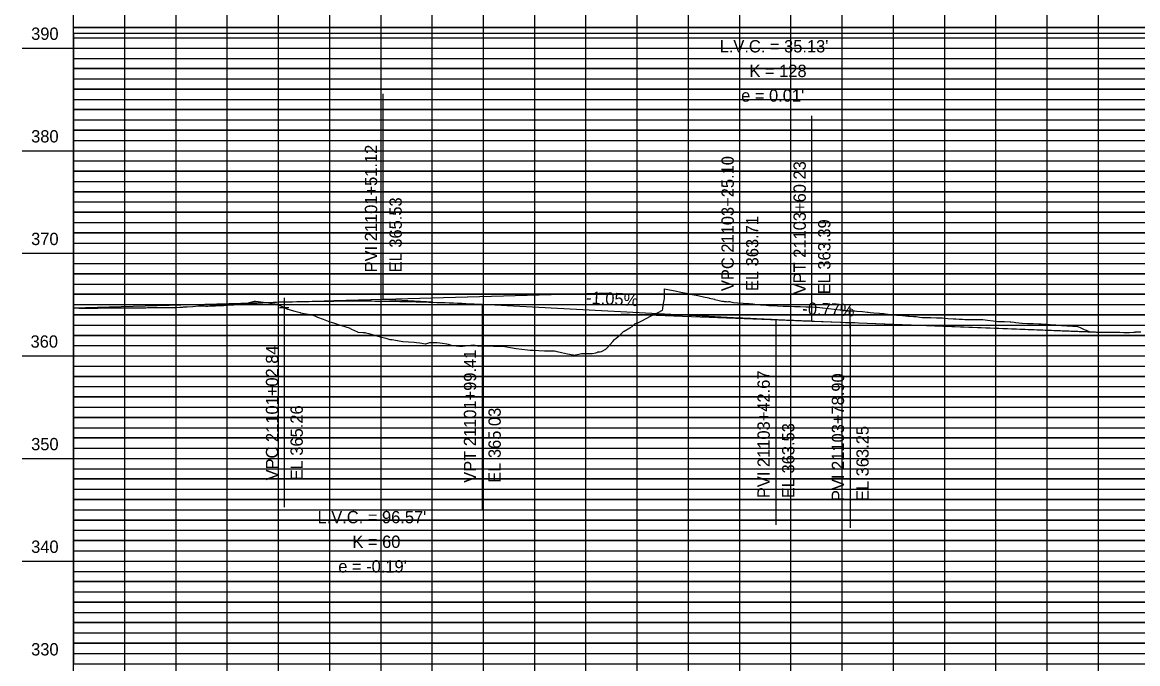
# Model space of a CAD drawing. Extents: x 1195880 to 1289360, y 2059330 to 2086925.
# Drawn here: x 1197037 to 1197582, y 2060795 to 2061108 of the extents above; entities that cross this region are included whole.
import ezdxf

# ---------------------------------------------------------------- set-up
doc = ezdxf.new("R2010")
doc.units = 0
for name, color, linetype in [('Clip', 7, 'Continuous'), ('Default', 7, 'Continuous'), ('Existing Ground PGL', 7, 'Continuous'), ('Grid', 7, 'Continuous'), ('Grid Lables', 7, 'Continuous'), ('Profile', 7, 'Continuous'), ('Profile Annotation', 7, 'Continuous')]:
    doc.layers.add(name, color=color, linetype=linetype)

msp = doc.modelspace()

# ---------------------------------------------------------------- linework, layer by layer
at = {"layer": 'Clip'}
msp.add_lwpolyline([(1197062.41, 2060795.23), (1197749.67, 2060795.23), (1197749.67, 2061102.29), (1197062.41, 2061102.29)], close=True, dxfattribs=at)
at = {"layer": 'Default'}
for p, q in [((1197062.41, 2060968.63), (1197324.45, 2060976.03)), ((1197165.25, 2060966.92), (1197165.25, 2060973.5)), ((1197162.75, 2060971.53), (1197167.48, 2060971.53)), ((1197162.91, 2060968.78), (1197167.48, 2060968.78)), ((1197438.95, 2060967.23), (1197443.57, 2060967.23)), ((1197441.31, 2060958.74), (1197441.31, 2060968.76)), ((1197329.61, 2060965.79), (1197560.99, 2060956.87)), ((1197438.95, 2060961.48), (1197443.57, 2060961.48))]:
    msp.add_line(p, q, dxfattribs=at)
at = {"layer": 'Existing Ground PGL'}
msp.add_lwpolyline([(1197062.41, 2060968.63), (1197064.09, 2060968.63), (1197065.18, 2060968.53), (1197065.19, 2060968.53), (1197065.95, 2060968.5), (1197066.05, 2060968.47), (1197067.95, 2060968.49), (1197069.77, 2060968.51), (1197070.72, 2060968.52), (1197073.49, 2060968.55), (1197074.28, 2060968.55), (1197076.25, 2060968.57), (1197077.47, 2060968.58), (1197079.02, 2060968.59), (1197081.09, 2060968.6), (1197081.79, 2060968.6), (1197083.51, 2060968.62), (1197084.56, 2060968.63), (1197084.89, 2060968.63), (1197087.33, 2060968.65), (1197088.65, 2060968.65), (1197090.1, 2060968.67), (1197091.99, 2060968.68), (1197092.87, 2060968.69), (1197093.23, 2060968.69), (1197095.64, 2060968.7), (1197096.24, 2060968.7), (1197097.36, 2060968.72), (1197097.75, 2060968.72), (1197098.41, 2060968.73), (1197101.17, 2060968.75), (1197101.19, 2060968.75), (1197102.71, 2060968.76), (1197103.94, 2060968.77), (1197104.75, 2060968.77), (1197106.71, 2060968.79), (1197107.16, 2060968.8), (1197108.1, 2060968.8), (1197109.48, 2060968.82), (1197111.2, 2060968.84), (1197111.29, 2060968.84), (1197111.63, 2060968.84), (1197112.25, 2060968.87), (1197114.32, 2060968.96), (1197114.97, 2060968.99), (1197115.02, 2060969), (1197115.75, 2060969.04), (1197116.08, 2060969.06), (1197117.79, 2060969.18), (1197120.56, 2060969.37), (1197123.33, 2060969.55), (1197123.85, 2060969.59), (1197126.1, 2060969.54), (1197126.89, 2060969.52), (1197127.7, 2060969.51), (1197128.86, 2060969.56), (1197131.63, 2060969.68), (1197134.4, 2060969.79), (1197135.61, 2060969.84), (1197137.17, 2060969.91), (1197139.94, 2060970.04), (1197140.67, 2060970.07), (1197142.27, 2060970.2), (1197142.71, 2060970.19), (1197144.29, 2060970.14), (1197144.39, 2060970.12), (1197144.7, 2060970.39), (1197145.48, 2060970.59), (1197148.25, 2060971.29), (1197150.62, 2060971.91), (1197150.83, 2060971.95), (1197150.89, 2060971.97), (1197150.98, 2060971.96), (1197151.02, 2060971.96), (1197151.11, 2060971.94), (1197153.79, 2060971.58), (1197156.55, 2060971.2), (1197159.32, 2060970.79), (1197161.97, 2060970.39), (1197162.09, 2060970.33), (1197164.86, 2060968.97), (1197166.79, 2060968.01), (1197167.63, 2060967.77), (1197168.55, 2060967.5), (1197170.4, 2060967.01), (1197172.99, 2060966.3), (1197173.17, 2060966.27), (1197175.94, 2060965.78), (1197178.06, 2060965.38), (1197178.71, 2060965.2), (1197179.58, 2060964.95), (1197180.37, 2060964.58), (1197181.47, 2060964.15), (1197184.24, 2060963.06), (1197186.56, 2060962.13), (1197187.01, 2060961.98), (1197189.78, 2060961.09), (1197192.55, 2060960.19), (1197194.68, 2060959.49), (1197195.32, 2060959.32), (1197196.84, 2060958.92), (1197198.09, 2060958.31), (1197200.86, 2060956.96), (1197201.15, 2060956.81), (1197203.63, 2060956.63), (1197204.47, 2060956.57), (1197205.04, 2060956.52), (1197206.4, 2060956.13), (1197209.16, 2060955.33), (1197211.93, 2060954.55), (1197214.7, 2060953.78), (1197216.72, 2060953.22), (1197217.47, 2060953.19), (1197217.81, 2060953.18), (1197220.24, 2060952.71), (1197220.42, 2060952.67), (1197223.01, 2060952.26), (1197223.02, 2060952.26), (1197225.78, 2060952.05), (1197228.55, 2060951.85), (1197229.68, 2060951.78), (1197231.32, 2060951.55), (1197234.09, 2060951.16), (1197234.26, 2060951.14), (1197236.3, 2060951.75), (1197236.85, 2060951.75), (1197239.62, 2060951.74), (1197239.78, 2060951.74), (1197242.39, 2060951.41), (1197244.53, 2060951.16), (1197245.16, 2060950.97), (1197247.17, 2060950.36), (1197247.93, 2060950.26), (1197250.18, 2060949.99), (1197250.59, 2060950.05), (1197250.7, 2060950.04), (1197252.38, 2060949.94), (1197253.47, 2060950.08), (1197256.24, 2060950.46), (1197257.63, 2060950.66), (1197259.01, 2060950.25), (1197259.99, 2060949.96), (1197261.78, 2060950.07), (1197263.05, 2060950.16), (1197264.54, 2060950.1), (1197267.31, 2060950.02), (1197269.26, 2060949.99), (1197270.08, 2060949.95), (1197271.88, 2060949.9), (1197272.85, 2060949.73), (1197275.62, 2060949.29), (1197278.39, 2060948.89), (1197281.16, 2060948.52), (1197283.93, 2060948.19), (1197285.2, 2060948.06), (1197286.7, 2060947.97), (1197289.46, 2060947.84), (1197292.23, 2060947.74), (1197295, 2060947.68), (1197296.17, 2060947.68), (1197297.08, 2060947.68), (1197297.77, 2060947.46), (1197298.24, 2060947.32), (1197299.75, 2060947.09), (1197300.54, 2060946.9), (1197303.31, 2060946.29), (1197306.08, 2060945.72), (1197306.53, 2060945.63), (1197308.85, 2060946.08), (1197310.29, 2060946.38), (1197311.62, 2060946.36), (1197314.39, 2060946.37), (1197315.41, 2060946.4), (1197317.15, 2060946.75), (1197317.66, 2060946.85), (1197318.16, 2060947.12), (1197319.4, 2060947.12), (1197319.92, 2060947.37), (1197322.06, 2060948.42), (1197322.69, 2060949.14), (1197325.46, 2060952.29), (1197326.27, 2060953.2), (1197327.92, 2060954.44), (1197328.23, 2060954.74), (1197330.78, 2060957.19), (1197331, 2060957.32), (1197333.77, 2060958.89), (1197334.88, 2060959.51), (1197336.31, 2060960.87), (1197336.54, 2060960.99), (1197337.01, 2060961.24), (1197337.71, 2060961.34), (1197339.31, 2060962.15), (1197339.37, 2060962.18), (1197342.08, 2060963.68), (1197343.55, 2060964.48), (1197344.84, 2060965.11), (1197347.61, 2060966.44), (1197349.71, 2060967.44), (1197349.93, 2060968.13), (1197350.11, 2060969.94), (1197350.38, 2060971.5), (1197350.68, 2060973.21), (1197350.73, 2060977.84), (1197353.15, 2060977.39), (1197355.92, 2060976.86), (1197358.69, 2060976.32), (1197361.46, 2060975.77), (1197364.23, 2060975.21), (1197366.19, 2060974.8), (1197367, 2060974.62), (1197367, 2060974.62), (1197369.77, 2060974.02), (1197372.34, 2060973.47), (1197372.54, 2060973.42), (1197375.1, 2060972.82), (1197375.31, 2060972.77), (1197376.65, 2060972.42), (1197378.08, 2060972.06), (1197378.67, 2060971.92), (1197379.28, 2060971.87), (1197379.75, 2060971.72), (1197380.85, 2060971.66), (1197381.25, 2060971.64), (1197381.92, 2060971.79), (1197382.48, 2060971.69), (1197383.62, 2060971.46), (1197384.41, 2060971.3), (1197386.4, 2060971.13), (1197389.17, 2060970.91), (1197391.94, 2060970.7), (1197393.76, 2060970.57), (1197394.48, 2060970.45), (1197394.71, 2060970.42), (1197396.46, 2060970.21), (1197397.48, 2060970.11), (1197397.72, 2060970.09), (1197400.25, 2060969.93), (1197401.61, 2060969.86), (1197403.02, 2060969.78), (1197405.8, 2060969.65), (1197408.57, 2060969.53), (1197411.34, 2060969.43), (1197411.74, 2060969.42), (1197414.11, 2060969.34), (1197416.88, 2060969.26), (1197419.65, 2060969.19), (1197421.03, 2060969.17), (1197422.42, 2060969.1), (1197424.1, 2060969.04), (1197425.19, 2060968.91), (1197427.87, 2060968.61), (1197427.97, 2060968.6), (1197430.74, 2060968.27), (1197433.51, 2060967.96), (1197436.28, 2060967.66), (1197436.56, 2060967.63), (1197437.15, 2060967.58), (1197437.95, 2060967.5), (1197438.27, 2060967.51), (1197439.05, 2060967.44), (1197441.82, 2060967.2), (1197444.59, 2060966.98), (1197447.37, 2060966.78), (1197449.78, 2060966.61), (1197450.14, 2060966.54), (1197451.08, 2060966.35), (1197452.91, 2060966.19), (1197455.68, 2060965.97), (1197457.72, 2060965.82), (1197458.45, 2060965.73), (1197461.22, 2060965.38), (1197462.34, 2060965.25), (1197463.99, 2060965.1), (1197466.76, 2060964.87), (1197469.54, 2060964.64), (1197470.13, 2060964.6), (1197472.14, 2060964.44), (1197472.31, 2060964.43), (1197473.48, 2060964.39), (1197475.08, 2060964.16), (1197476.4, 2060963.98), (1197477.85, 2060963.99), (1197480.53, 2060964.01), (1197480.62, 2060964), (1197483.39, 2060963.85), (1197486.16, 2060963.71), (1197486.41, 2060963.7), (1197488.94, 2060963.51), (1197491.71, 2060963.32), (1197492.92, 2060963.24), (1197494.48, 2060963.15), (1197496.05, 2060963.07), (1197497.25, 2060962.93), (1197497.57, 2060962.89), (1197500.02, 2060962.92), (1197502.79, 2060962.97), (1197504.47, 2060963.01), (1197505.56, 2060963.02), (1197506.08, 2060963.02), (1197508.34, 2060962.7), (1197511.11, 2060962.33), (1197513.21, 2060962.05), (1197513.88, 2060962.02), (1197516.65, 2060961.95), (1197519.42, 2060961.88), (1197519.69, 2060961.88), (1197521.36, 2060961.69), (1197522.19, 2060961.56), (1197524.96, 2060961.15), (1197525.16, 2060961.12), (1197527.73, 2060961.02), (1197530.51, 2060960.93), (1197533.28, 2060960.86), (1197534.43, 2060960.83), (1197536.05, 2060960.7), (1197537.39, 2060960.61), (1197538.82, 2060960.52), (1197541.39, 2060960.36), (1197541.59, 2060960.34), (1197543.59, 2060960.13), (1197544.36, 2060960.07), (1197547.13, 2060959.85), (1197549.91, 2060959.65), (1197552.21, 2060959.5), (1197552.68, 2060959.32), (1197553.49, 2060959.05), (1197555.45, 2060958.14), (1197556.41, 2060957.75), (1197558.22, 2060957.01), (1197558.46, 2060956.92), (1197560.99, 2060956.87), (1197561.71, 2060956.85), (1197562.78, 2060956.8), (1197563.22, 2060956.81), (1197563.76, 2060956.8), (1197566.53, 2060956.77), (1197569.3, 2060956.73), (1197569.33, 2060956.73), (1197569.38, 2060956.73), (1197569.43, 2060956.73), (1197571.95, 2060956.77), (1197572.08, 2060956.77), (1197572.82, 2060956.78), (1197574.85, 2060956.67), (1197576.71, 2060956.58), (1197576.96, 2060956.58), (1197577.17, 2060956.58), (1197577.62, 2060956.62), (1197579.54, 2060956.78), (1197580.26, 2060956.86), (1197580.39, 2060956.88), (1197580.61, 2060956.9), (1197580.81, 2060956.92), (1197580.94, 2060956.93), (1197581.04, 2060956.94), (1197581.1, 2060956.95), (1197583.16, 2060956.95)], dxfattribs=at)
at = {"layer": 'Grid'}
for p, q in [((1197062.41, 2060695.23), (1197062.41, 2061245.23)), ((1197087.41, 2060695.23), (1197087.41, 2061245.23)), ((1197112.41, 2060695.23), (1197112.41, 2061245.23)), ((1197137.41, 2060695.23), (1197137.41, 2061245.23)), ((1197162.41, 2060695.23), (1197162.41, 2061245.23)), ((1197187.41, 2060695.23), (1197187.41, 2061245.23)), ((1197212.41, 2060695.23), (1197212.41, 2061245.23)), ((1197237.41, 2060695.23), (1197237.41, 2061245.23)), ((1197262.41, 2060695.23), (1197262.41, 2061245.23)), ((1197287.41, 2060695.23), (1197287.41, 2061245.23)), ((1197312.41, 2060695.23), (1197312.41, 2061245.23)), ((1197337.41, 2060695.23), (1197337.41, 2061245.23)), ((1197362.41, 2060695.23), (1197362.41, 2061245.23)), ((1197387.41, 2060695.23), (1197387.41, 2061245.23)), ((1197412.41, 2060695.23), (1197412.41, 2061245.23)), ((1197437.41, 2060695.23), (1197437.41, 2061245.23)), ((1197462.41, 2060695.23), (1197462.41, 2061245.23)), ((1197487.41, 2060695.23), (1197487.41, 2061245.23)), ((1197512.41, 2060695.23), (1197512.41, 2061245.23)), ((1197537.41, 2060695.23), (1197537.41, 2061245.23)), ((1197562.41, 2060695.23), (1197562.41, 2061245.23)), ((1197062.41, 2061105.23), (1197065.41, 2061105.23)), ((1197062.41, 2061105.23), (1198062.41, 2061105.23)), ((1198062.41, 2061105.23), (1197062.41, 2061105.23)), ((1197062.41, 2061100.23), (1197065.41, 2061100.23)), ((1197062.41, 2061100.23), (1198062.41, 2061100.23)), ((1197037.41, 2061095.23), (1197062.41, 2061095.23)), ((1197062.41, 2061095.23), (1198062.41, 2061095.23)), ((1197062.41, 2061090.23), (1197065.41, 2061090.23)), ((1197062.41, 2061090.23), (1198062.41, 2061090.23)), ((1197062.41, 2061085.23), (1197065.41, 2061085.23)), ((1197062.41, 2061085.23), (1198062.41, 2061085.23)), ((1198062.41, 2061085.23), (1197062.41, 2061085.23)), ((1197062.41, 2061080.23), (1197065.41, 2061080.23)), ((1197062.41, 2061080.23), (1198062.41, 2061080.23)), ((1197062.41, 2061075.23), (1197065.41, 2061075.23)), ((1197062.41, 2061075.23), (1198062.41, 2061075.23)), ((1198062.41, 2061075.23), (1197062.41, 2061075.23)), ((1197062.41, 2061070.23), (1197065.41, 2061070.23)), ((1197062.41, 2061070.23), (1198062.41, 2061070.23)), ((1197062.41, 2061065.23), (1197065.41, 2061065.23)), ((1197062.41, 2061065.23), (1198062.41, 2061065.23)), ((1198062.41, 2061065.23), (1197062.41, 2061065.23)), ((1197062.41, 2061060.23), (1197065.41, 2061060.23)), ((1197062.41, 2061060.23), (1198062.41, 2061060.23)), ((1197062.41, 2061055.23), (1197065.41, 2061055.23)), ((1197062.41, 2061055.23), (1198062.41, 2061055.23)), ((1198062.41, 2061055.23), (1197062.41, 2061055.23)), ((1197062.41, 2061050.23), (1197065.41, 2061050.23)), ((1197062.41, 2061050.23), (1198062.41, 2061050.23)), ((1197037.41, 2061045.23), (1197062.41, 2061045.23)), ((1197062.41, 2061045.23), (1198062.41, 2061045.23)), ((1197062.41, 2061040.23), (1197065.41, 2061040.23)), ((1197062.41, 2061040.23), (1198062.41, 2061040.23)), ((1197062.41, 2061035.23), (1197065.41, 2061035.23)), ((1197062.41, 2061035.23), (1198062.41, 2061035.23)), ((1198062.41, 2061035.23), (1197062.41, 2061035.23)), ((1197062.41, 2061030.23), (1197065.41, 2061030.23)), ((1197062.41, 2061030.23), (1198062.41, 2061030.23)), ((1197062.41, 2061025.23), (1197065.41, 2061025.23)), ((1197062.41, 2061025.23), (1198062.41, 2061025.23)), ((1198062.41, 2061025.23), (1197062.41, 2061025.23)), ((1197062.41, 2061020.23), (1197065.41, 2061020.23)), ((1197062.41, 2061020.23), (1198062.41, 2061020.23)), ((1197062.41, 2061015.23), (1197065.41, 2061015.23)), ((1197062.41, 2061015.23), (1198062.41, 2061015.23)), ((1198062.41, 2061015.23), (1197062.41, 2061015.23)), ((1197062.41, 2061010.23), (1197065.41, 2061010.23)), ((1197062.41, 2061010.23), (1198062.41, 2061010.23)), ((1197062.41, 2061005.23), (1197065.41, 2061005.23)), ((1197062.41, 2061005.23), (1198062.41, 2061005.23)), ((1198062.41, 2061005.23), (1197062.41, 2061005.23)), ((1197062.41, 2061000.23), (1197065.41, 2061000.23)), ((1197062.41, 2061000.23), (1198062.41, 2061000.23)), ((1197037.41, 2060995.23), (1197062.41, 2060995.23)), ((1197062.41, 2060995.23), (1198062.41, 2060995.23)), ((1197062.41, 2060990.23), (1197065.41, 2060990.23)), ((1197062.41, 2060990.23), (1198062.41, 2060990.23)), ((1197062.41, 2060985.23), (1197065.41, 2060985.23)), ((1197062.41, 2060985.23), (1198062.41, 2060985.23)), ((1198062.41, 2060985.23), (1197062.41, 2060985.23)), ((1197062.41, 2060980.23), (1197065.41, 2060980.23)), ((1197062.41, 2060980.23), (1198062.41, 2060980.23)), ((1197062.41, 2060975.23), (1197065.41, 2060975.23)), ((1197062.41, 2060975.23), (1198062.41, 2060975.23)), ((1198062.41, 2060975.23), (1197062.41, 2060975.23)), ((1197062.41, 2060970.23), (1197065.41, 2060970.23)), ((1197062.41, 2060970.23), (1198062.41, 2060970.23)), ((1197062.41, 2060965.23), (1197065.41, 2060965.23)), ((1197062.41, 2060965.23), (1198062.41, 2060965.23)), ((1198062.41, 2060965.23), (1197062.41, 2060965.23)), ((1197062.41, 2060960.23), (1197065.41, 2060960.23)), ((1197062.41, 2060960.23), (1198062.41, 2060960.23)), ((1197062.41, 2060955.23), (1197065.41, 2060955.23)), ((1197062.41, 2060955.23), (1198062.41, 2060955.23)), ((1198062.41, 2060955.23), (1197062.41, 2060955.23)), ((1197062.41, 2060950.23), (1197065.41, 2060950.23)), ((1197062.41, 2060950.23), (1198062.41, 2060950.23)), ((1197037.41, 2060945.23), (1197062.41, 2060945.23)), ((1197062.41, 2060945.23), (1198062.41, 2060945.23)), ((1197062.41, 2060940.23), (1197065.41, 2060940.23)), ((1197062.41, 2060940.23), (1198062.41, 2060940.23)), ((1197062.41, 2060935.23), (1197065.41, 2060935.23)), ((1197062.41, 2060935.23), (1198062.41, 2060935.23)), ((1198062.41, 2060935.23), (1197062.41, 2060935.23)), ((1197062.41, 2060930.23), (1197065.41, 2060930.23)), ((1197062.41, 2060930.23), (1198062.41, 2060930.23)), ((1197062.41, 2060925.23), (1197065.41, 2060925.23)), ((1197062.41, 2060925.23), (1198062.41, 2060925.23)), ((1198062.41, 2060925.23), (1197062.41, 2060925.23)), ((1197062.41, 2060920.23), (1197065.41, 2060920.23)), ((1197062.41, 2060920.23), (1198062.41, 2060920.23)), ((1197062.41, 2060915.23), (1197065.41, 2060915.23)), ((1197062.41, 2060915.23), (1198062.41, 2060915.23)), ((1198062.41, 2060915.23), (1197062.41, 2060915.23)), ((1197062.41, 2060910.23), (1197065.41, 2060910.23)), ((1197062.41, 2060910.23), (1198062.41, 2060910.23)), ((1197062.41, 2060905.23), (1197065.41, 2060905.23)), ((1197062.41, 2060905.23), (1198062.41, 2060905.23)), ((1198062.41, 2060905.23), (1197062.41, 2060905.23)), ((1197062.41, 2060900.23), (1197065.41, 2060900.23)), ((1197062.41, 2060900.23), (1198062.41, 2060900.23)), ((1197037.41, 2060895.23), (1197062.41, 2060895.23)), ((1197062.41, 2060895.23), (1198062.41, 2060895.23)), ((1197062.41, 2060890.23), (1197065.41, 2060890.23)), ((1197062.41, 2060890.23), (1198062.41, 2060890.23)), ((1197062.41, 2060885.23), (1197065.41, 2060885.23)), ((1197062.41, 2060885.23), (1198062.41, 2060885.23)), ((1198062.41, 2060885.23), (1197062.41, 2060885.23)), ((1197062.41, 2060880.23), (1197065.41, 2060880.23)), ((1197062.41, 2060880.23), (1198062.41, 2060880.23)), ((1197062.41, 2060875.23), (1197065.41, 2060875.23)), ((1197062.41, 2060875.23), (1198062.41, 2060875.23)), ((1198062.41, 2060875.23), (1197062.41, 2060875.23)), ((1197062.41, 2060870.23), (1197065.41, 2060870.23)), ((1197062.41, 2060870.23), (1198062.41, 2060870.23)), ((1197062.41, 2060865.23), (1197065.41, 2060865.23)), ((1197062.41, 2060865.23), (1198062.41, 2060865.23)), ((1198062.41, 2060865.23), (1197062.41, 2060865.23)), ((1197062.41, 2060860.23), (1197065.41, 2060860.23)), ((1197062.41, 2060860.23), (1198062.41, 2060860.23)), ((1197062.41, 2060855.23), (1197065.41, 2060855.23)), ((1197062.41, 2060855.23), (1198062.41, 2060855.23)), ((1198062.41, 2060855.23), (1197062.41, 2060855.23)), ((1197062.41, 2060850.23), (1197065.41, 2060850.23)), ((1197062.41, 2060850.23), (1198062.41, 2060850.23)), ((1197037.41, 2060845.23), (1197062.41, 2060845.23)), ((1197062.41, 2060845.23), (1198062.41, 2060845.23)), ((1197062.41, 2060840.23), (1197065.41, 2060840.23)), ((1197062.41, 2060840.23), (1198062.41, 2060840.23)), ((1197062.41, 2060835.23), (1197065.41, 2060835.23)), ((1197062.41, 2060835.23), (1198062.41, 2060835.23)), ((1198062.41, 2060835.23), (1197062.41, 2060835.23)), ((1197062.41, 2060830.23), (1197065.41, 2060830.23)), ((1197062.41, 2060830.23), (1198062.41, 2060830.23)), ((1197062.41, 2060825.23), (1197065.41, 2060825.23)), ((1197062.41, 2060825.23), (1198062.41, 2060825.23)), ((1198062.41, 2060825.23), (1197062.41, 2060825.23)), ((1197062.41, 2060820.23), (1197065.41, 2060820.23)), ((1197062.41, 2060820.23), (1198062.41, 2060820.23)), ((1197062.41, 2060815.23), (1197065.41, 2060815.23)), ((1197062.41, 2060815.23), (1198062.41, 2060815.23)), ((1198062.41, 2060815.23), (1197062.41, 2060815.23)), ((1197062.41, 2060810.23), (1197065.41, 2060810.23)), ((1197062.41, 2060810.23), (1198062.41, 2060810.23)), ((1197062.41, 2060805.23), (1197065.41, 2060805.23)), ((1197062.41, 2060805.23), (1198062.41, 2060805.23)), ((1198062.41, 2060805.23), (1197062.41, 2060805.23)), ((1197062.41, 2060800.23), (1197065.41, 2060800.23)), ((1197062.41, 2060800.23), (1198062.41, 2060800.23))]:
    msp.add_line(p, q, dxfattribs=at)
at = {"layer": 'Profile'}
for p, q in [((1197165.11, 2060971.53), (1197141.47, 2060970.14)), ((1197261.82, 2060970.37), (1197387.51, 2060963.8)), ((1197422.64, 2060962.2), (1197441.31, 2060961.48)), ((1197441.26, 2060961.48), (1197561.35, 2060956.86))]:
    msp.add_line(p, q, dxfattribs=at)
for points in [[(1197165.25, 2060971.53), (1197167.26, 2060971.59), (1197169.27, 2060971.64), (1197171.28, 2060971.69), (1197173.3, 2060971.73), (1197175.31, 2060971.77), (1197177.32, 2060971.81), (1197179.33, 2060971.85), (1197181.34, 2060971.88), (1197183.36, 2060971.91), (1197185.37, 2060971.93), (1197187.38, 2060971.95), (1197189.39, 2060971.97), (1197191.4, 2060971.99), (1197193.41, 2060972), (1197195.43, 2060972.01), (1197197.44, 2060972.01), (1197199.45, 2060972.01), (1197201.46, 2060972.01), (1197203.47, 2060972), (1197205.49, 2060971.99), (1197207.5, 2060971.98), (1197209.51, 2060971.97), (1197211.52, 2060971.95), (1197215.54, 2060971.9), (1197217.56, 2060971.87), (1197219.57, 2060971.84), (1197221.58, 2060971.8), (1197223.59, 2060971.76), (1197225.6, 2060971.72), (1197227.62, 2060971.67), (1197229.63, 2060971.62), (1197231.64, 2060971.57), (1197233.65, 2060971.51), (1197235.66, 2060971.45), (1197237.67, 2060971.39), (1197239.69, 2060971.32), (1197241.7, 2060971.25), (1197243.71, 2060971.18), (1197245.72, 2060971.1), (1197247.73, 2060971.02), (1197249.75, 2060970.94), (1197251.76, 2060970.85), (1197253.77, 2060970.76), (1197255.78, 2060970.67), (1197257.79, 2060970.57), (1197259.8, 2060970.47), (1197261.82, 2060970.37)], [(1197387.51, 2060963.8), (1197388.24, 2060963.76), (1197388.97, 2060963.72), (1197389.71, 2060963.68), (1197390.44, 2060963.65), (1197391.17, 2060963.61), (1197391.9, 2060963.57), (1197392.63, 2060963.54), (1197393.37, 2060963.5), (1197394.1, 2060963.46), (1197394.83, 2060963.43), (1197395.56, 2060963.39), (1197396.29, 2060963.35), (1197397.02, 2060963.32), (1197397.76, 2060963.28), (1197398.49, 2060963.25), (1197399.22, 2060963.21), (1197399.95, 2060963.18), (1197400.68, 2060963.14), (1197401.42, 2060963.11), (1197402.15, 2060963.08), (1197402.88, 2060963.04), (1197403.61, 2060963.01), (1197404.34, 2060962.97), (1197405.81, 2060962.91), (1197406.54, 2060962.87), (1197407.27, 2060962.84), (1197408, 2060962.81), (1197408.73, 2060962.78), (1197409.47, 2060962.74), (1197410.2, 2060962.71), (1197410.93, 2060962.68), (1197411.66, 2060962.65), (1197412.39, 2060962.62), (1197413.12, 2060962.59), (1197413.86, 2060962.56), (1197414.59, 2060962.53), (1197415.32, 2060962.5), (1197416.05, 2060962.47), (1197416.78, 2060962.44), (1197417.52, 2060962.41), (1197418.25, 2060962.38), (1197418.98, 2060962.35), (1197419.71, 2060962.32), (1197420.44, 2060962.29), (1197421.17, 2060962.26), (1197421.91, 2060962.23), (1197422.64, 2060962.2)]]:
    msp.add_lwpolyline(points, dxfattribs=at)
at = {"layer": 'Profile Annotation'}
for p, q in [((1197213.53, 2060972.9), (1197213.53, 2061072.9)), ((1197387.51, 2060963.8), (1197387.51, 2061063.8)), ((1197422.64, 2060962.2), (1197422.64, 2061062.2)), ((1197189.39, 2060972.21), (1197213.53, 2060972.9)), ((1197213.53, 2060972.9), (1197237.67, 2060971.63)), ((1197165.25, 2060871.53), (1197165.25, 2060971.53)), ((1197261.82, 2060970.37), (1197261.82, 2060870.37)), ((1197396.29, 2060963.34), (1197405.07, 2060962.88)), ((1197405.07, 2060962.88), (1197413.86, 2060962.54)), ((1197405.07, 2060962.88), (1197405.07, 2060862.88)), ((1197441.31, 2060961.48), (1197441.31, 2060861.48))]:
    msp.add_line(p, q, dxfattribs=at)

# ---------------------------------------------------------------- texts
at = {"layer": 'Grid Lables'}
for s, p in [('390', (1197041.72, 2061099.23)), ('380', (1197041.72, 2061049.23)), ('370', (1197041.72, 2060999.23)), ('360', (1197041.43, 2060949.23)), ('350', (1197041.72, 2060899.23)), ('340', (1197041.72, 2060849.23)), ('330', (1197041.72, 2060799.23))]:
    msp.add_text(s, height=6, dxfattribs=at).set_placement(p)
at = {"layer": 'Profile Annotation'}
for s, p in [("L.V.C. = 35.13'", (1197377.62, 2061093.11)), ('K = 128', (1197392.17, 2061081.11)), ("e = 0.01'", (1197388.11, 2061069.11)), ("L.V.C. = 96.57'", (1197181.45, 2060863.65)), ('K = 60', (1197198.44, 2060851.65)), ("e = -0.19'", (1197191.56, 2060839.65))]:
    msp.add_text(s, height=6, dxfattribs=at).set_placement(p)
for s, rotation, p in [('PVI 21101+51.12', 90, (1197210.53, 2060985.9)), ('VPC 21103+25.10', 90, (1197384.51, 2060976.8)), ('VPT 21103+60.23', 90, (1197419.64, 2060975.2)), ('EL 365.53', 90, (1197222.53, 2060985.9)), ('EL 363.71', 90, (1197396.51, 2060976.8)), ('EL 363.39', 90, (1197431.64, 2060975.2)), ('-1.05%', 357.0067, (1197312.34, 2060970.73)), ('-0.77%', 357.7913, (1197417.9, 2060965.39)), ('VPC 21101+02.84', 90, (1197162.25, 2060884.53)), ('VPT 21101+99.41', 90, (1197258.82, 2060883.37)), ('PVI 21103+42.67', 90, (1197402.07, 2060875.88)), ('PVI 21103+78.90', 90, (1197438.31, 2060874.48)), ('EL 365.26', 90, (1197174.25, 2060884.53)), ('EL 365.03', 90, (1197270.82, 2060883.37)), ('EL 363.53', 90, (1197414.07, 2060875.88)), ('EL 363.25', 90, (1197450.31, 2060874.48))]:
    msp.add_text(s, height=6, rotation=rotation, dxfattribs=at).set_placement(p)

doc.saveas('drawing.dxf')
